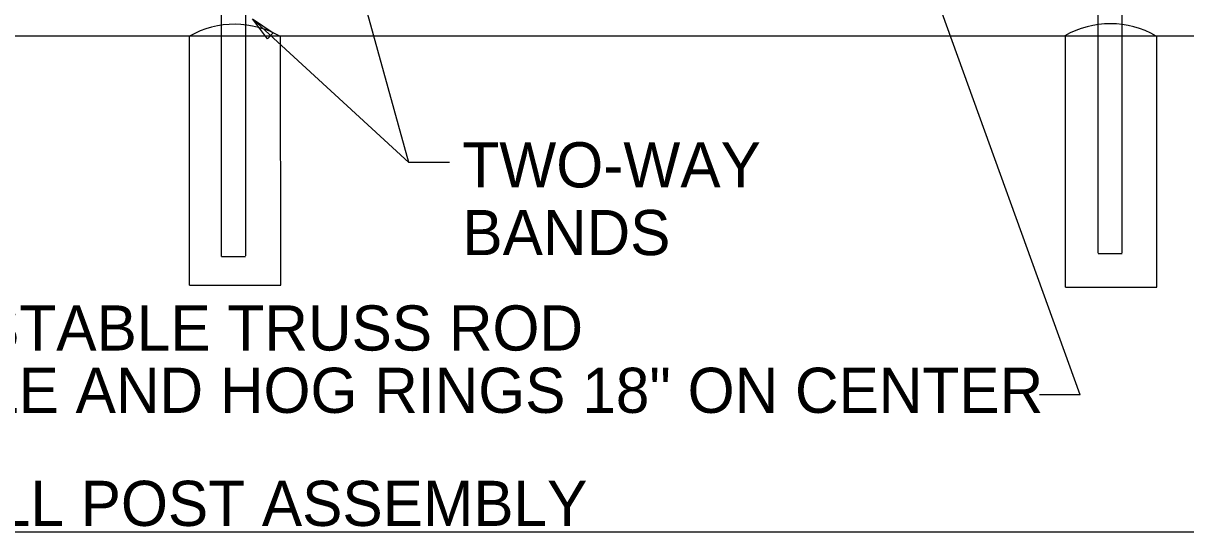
# Model space of a CAD drawing. Extents: x 0 to 2.85, y -0.1 to 1.83.
# Drawn here: x 1.4431 to 1.7006, y 0.6958 to 0.8084 of the extents above; entities that cross this region are included whole.
import ezdxf

# ---------------------------------------------------------------- set-up
doc = ezdxf.new("R2010")
doc.units = 0
for name, color, linetype in [('CT_CSHT_GeneralLabel', 7, 'Continuous'), ('CT_Dimensions', 7, 'Continuous'), ('sb_Chainlink Fence', 7, 'Continuous'), ('sb_Existing Concrete', 7, 'Continuous'), ('sb_Existing Structural Steel', 7, 'Continuous')]:
    doc.layers.add(name, color=color, linetype=linetype)

msp = doc.modelspace()

# ---------------------------------------------------------------- linework, layer by layer
at = {"layer": 'CT_Dimensions'}
msp.add_line((1.09949, 0.6958), (1.87875, 0.6958), dxfattribs=at)
at = {"layer": 'sb_Chainlink Fence'}
for p, q in [((1.52852, 0.77753), (1.49277, 0.90653)), ((1.67721, 0.72608), (1.6242, 0.87258)), ((1.52852, 0.77753), (1.49393, 0.8093)), ((1.26429, 0.80554), (1.88005, 0.80558)), ((1.53754, 0.77753), (1.52852, 0.77753)), ((1.67721, 0.72608), (1.66818, 0.72608))]:
    msp.add_line(p, q, dxfattribs=at)
msp.add_lwpolyline([(1.49719, 0.80491), (1.49387, 0.80938), (1.49846, 0.80622)], close=True, dxfattribs=at)
at = {"layer": 'sb_Existing Concrete'}
for p, q in [((1.47992, 0.75036), (1.4799, 0.80549)), ((1.50013, 0.75036), (1.50011, 0.80543)), ((1.67391, 0.74994), (1.67391, 0.80544)), ((1.69412, 0.74998), (1.69412, 0.8056)), ((1.47992, 0.75036), (1.50013, 0.75036)), ((1.6739, 0.74998), (1.69415, 0.74998))]:
    msp.add_line(p, q, dxfattribs=at)
for centre in [(1.48995, 0.78786), (1.68382, 0.78798)]:
    msp.add_arc(centre, 0.02029, 59.953, 119.6876, dxfattribs=at)
at = {"layer": 'sb_Existing Structural Steel'}
for p, q in [((1.487, 0.80788), (1.487, 0.92699)), ((1.49243, 0.80795), (1.49243, 0.92703)), ((1.6812, 0.80768), (1.6812, 0.91688)), ((1.68649, 0.80761), (1.68649, 0.91708)), ((1.487, 0.75672), (1.487, 0.80788)), ((1.49243, 0.75687), (1.49243, 0.80795)), ((1.6812, 0.7575), (1.6812, 0.80768)), ((1.68649, 0.75757), (1.68649, 0.80761)), ((1.68115, 0.75742), (1.6865, 0.75742)), ((1.487, 0.75672), (1.49235, 0.75672))]:
    msp.add_line(p, q, dxfattribs=at)

# ---------------------------------------------------------------- texts
at = {"layer": 'CT_CSHT_GeneralLabel'}
msp.add_text('PULL POST ASSEMBLY', height=0.01, dxfattribs=at).set_placement((1.41867, 0.69708))
at = {"layer": 'CT_Dimensions'}
for s, p in [('TWO-WAY ', (1.54037, 0.77203)), ('BANDS', (1.54037, 0.75703)), ("⅜'' DIA. ADJUSTABLE TRUSS ROD", (1.34873, 0.73591)), ('WITH TURNBUCKLE AND HOG RINGS 18" ON CENTER', (1.32248, 0.72211))]:
    msp.add_text(s, height=0.01, dxfattribs=at).set_placement(p)

doc.saveas('drawing.dxf')
